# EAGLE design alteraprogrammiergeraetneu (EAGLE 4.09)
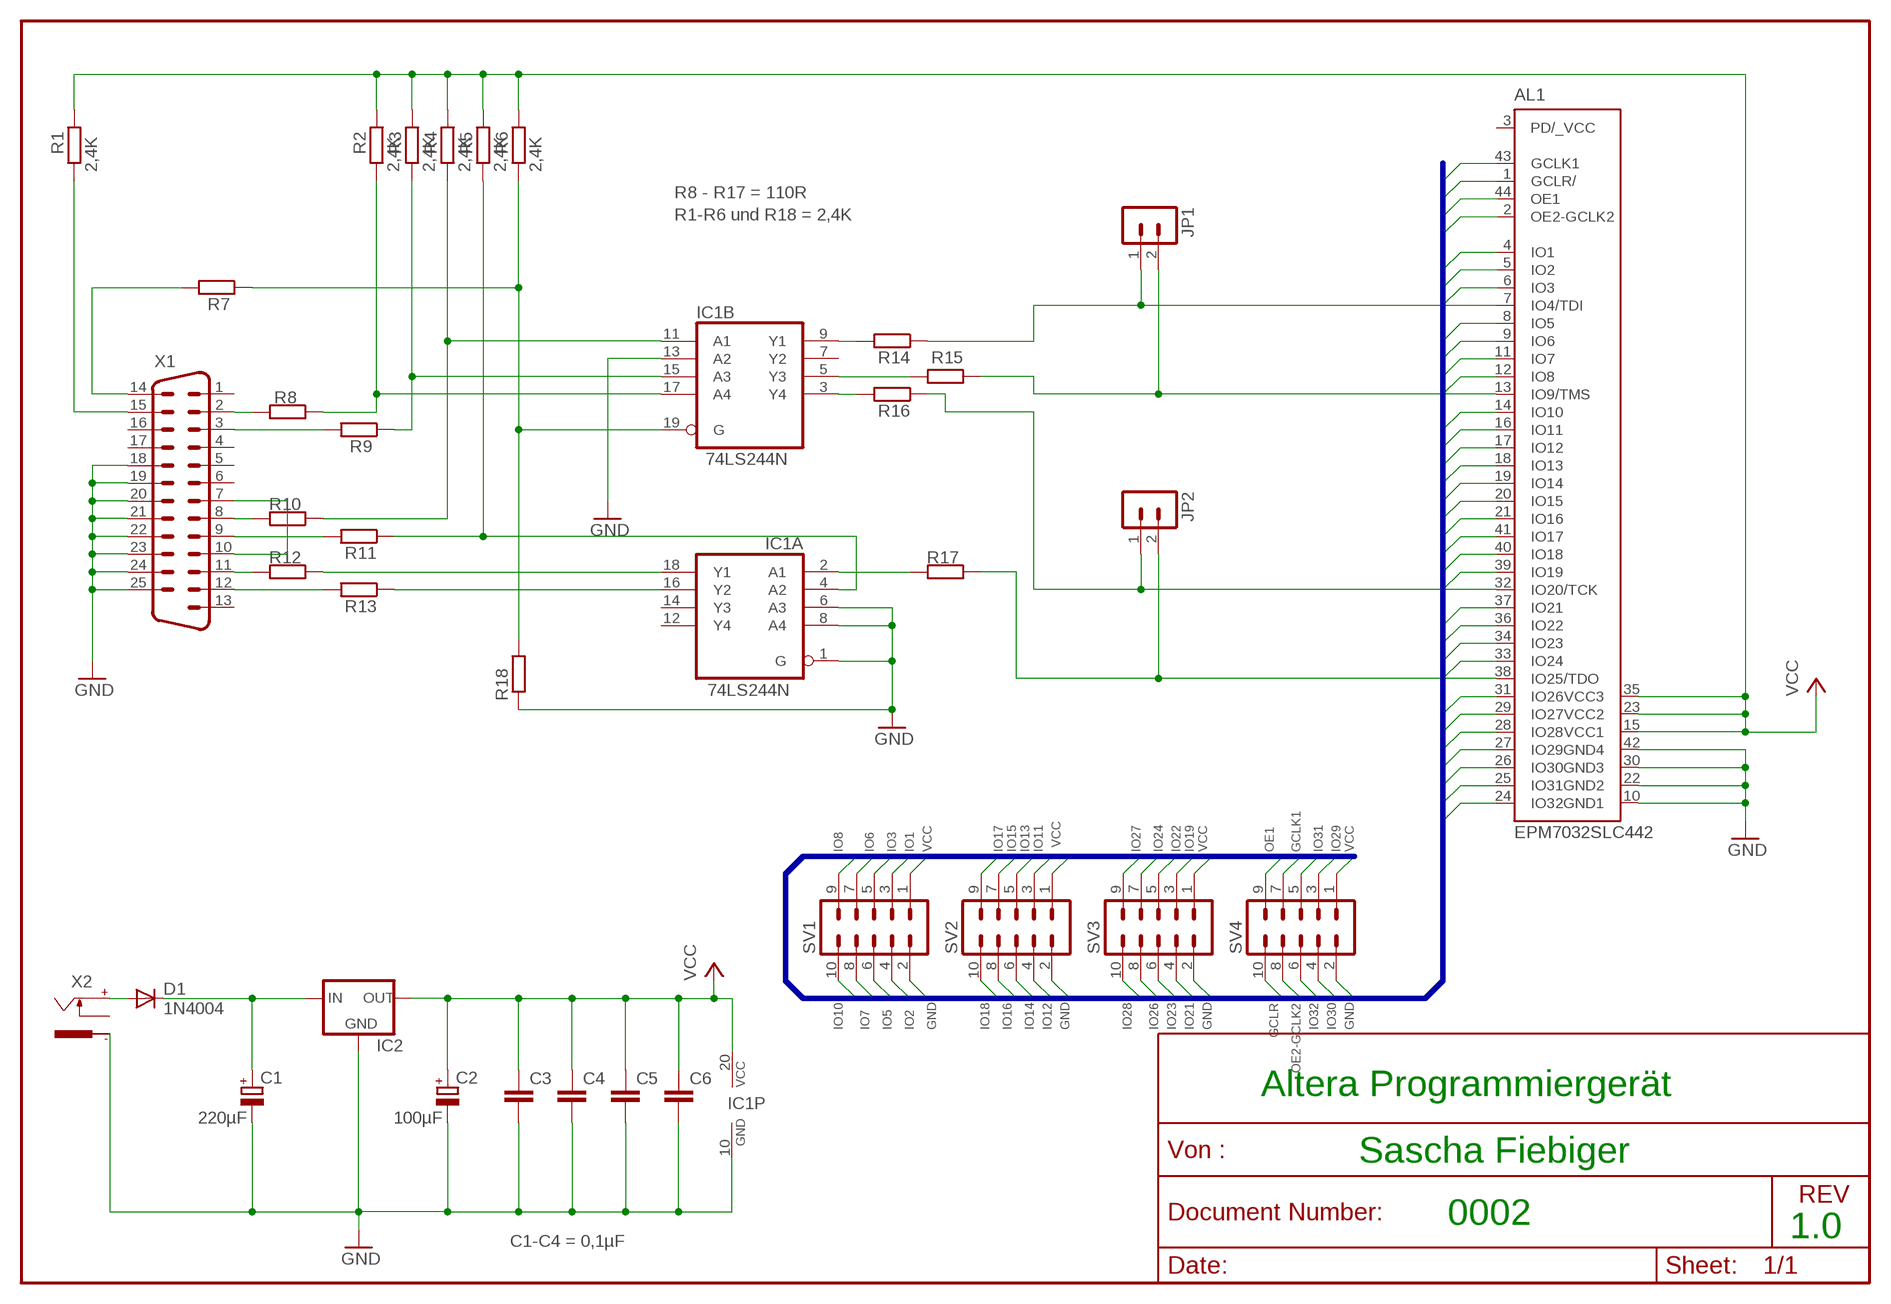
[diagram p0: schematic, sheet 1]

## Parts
AL1  EPM7032SLC442  [PLCC442]
C1  220µF  CPOL-EUE3.5-8  [E3,5-8]
C2  100µF  CPOL-EUE3.5-8  [E3,5-8]
C3  C-EU050-025X075  [C050-025X075]
C4  C-EU050-025X075  [C050-025X075]
C5  C-EU050-025X075  [C050-025X075]
C6  C-EU050-025X075  [C050-025X075]
D1  1N4004  [DO41-10]
IC1  74LS244N  [DIL20]
IC2  78XXS  [78XXS]
JP1  2POL  [2POL]
JP2  2POL  [2POL]
R1  2,4K  R-EU_0207/10  [0207/10]
R2  2,4K  R-EU_0207/10  [0207/10]
R3  2,4K  R-EU_0207/10  [0207/10]
R4  2,4K  R-EU_0207/10  [0207/10]
R5  2,4K  R-EU_0207/10  [0207/10]
R6  2,4K  R-EU_0207/10  [0207/10]
R7  R-EU_0207/10  [0207/10]
R8  R-EU_0207/10  [0207/10]
R9  R-EU_0207/10  [0207/10]
R10  R-EU_0207/10  [0207/10]
R11  R-EU_0207/10  [0207/10]
R12  R-EU_0207/10  [0207/10]
R13  R-EU_0207/10  [0207/10]
R14  R-EU_0207/10  [0207/10]
R15  R-EU_0207/10  [0207/10]
R16  R-EU_0207/10  [0207/10]
R17  R-EU_0207/10  [0207/10]
R18  R-EU_0207/10  [0207/10]
SV1  ML10  [ML10]
SV2  ML10  [ML10]
SV3  ML10  [ML10]
SV4  ML10  [ML10]
X1  M25H  [M25H]
X2  737992-55  [737992-5]

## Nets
GCLK1: AL1.43(GCLK1) SV4.7
GCLR: AL1.1(GCLR/) SV4.10
GND: AL1.10(GND1) AL1.22(GND2) AL1.30(GND3) AL1.42(GND4) C1.- C2.- C3.2 C4.2 C5.2 C6.2 IC1.1(A:G) IC1.6(A:A3) IC1.8(A:A4) IC1.10(P:GND) IC1.13(B:A2) IC2.GND R18.1 SV1.2 SV2.2 SV3.2 SV4.2 X1.18 X1.19 X1.20 X1.21 X1.22 X1.23 X1.24 X1.25 X2.-1
IO1: AL1.4(IO1) SV1.3
IO2: AL1.5(IO2) SV1.4
IO3: AL1.6(IO3) SV1.5
IO5: AL1.8(IO5) SV1.6
IO6: AL1.9(IO6) SV1.7
IO7: AL1.11(IO7) SV1.8
IO8: AL1.12(IO8) SV1.9
IO10: AL1.14(IO10) SV1.10
IO11: AL1.16(IO11) SV2.3
IO12: AL1.17(IO12) SV2.4
IO13: AL1.18(IO13) SV2.5
IO14: AL1.19(IO14) SV2.6
IO15: AL1.20(IO15) SV2.7
IO16: AL1.21(IO16) SV2.8
IO17: AL1.41(IO17) SV2.9
IO18: AL1.40(IO18) SV2.10
IO19: AL1.39(IO19) SV3.3
IO21: AL1.37(IO21) SV3.4
IO22: AL1.36(IO22) SV3.5
IO23: AL1.34(IO23) SV3.6
IO24: AL1.33(IO24) SV3.7
IO26: AL1.31(IO26) SV3.8
IO27: AL1.29(IO27) SV3.9
IO28: AL1.28(IO28) SV3.10
IO29: AL1.27(IO29) SV4.3
IO30: AL1.26(IO30) SV4.4
IO31: AL1.25(IO31) SV4.5
IO32: AL1.24(IO32) SV4.6
N$1: IC1.18(A:Y1) R12.1
N$2: R8.2 X1.2
N$3: R9.2 X1.3
N$4: R10.2 X1.8
N$5: R11.2 X1.9
N$6: R12.2 X1.11
N$7: R13.2 X1.12
N$8: R7.2 X1.14
N$9: R1.1 X1.15
N$10: D1.A X2.+
N$11: IC1.11(B:A1) R4.1 R10.1
N$12: IC1.4(A:A2) R5.1 R11.1
N$13: C1.+ D1.C IC2.IN
N$14: IC1.15(B:A3) R3.1 R9.1
N$15: IC1.17(B:A4) R2.1 R8.1
N$16: IC1.19(B:G) R6.1 R7.1 R18.2
N$17: IC1.16(A:Y2) R13.1
N$22: X1.7 X1.10
N$23: IC1.9(B:Y1) R14.2
N$24: IC1.5(B:Y3) R15.2
N$25: IC1.3(B:Y4) R16.2
N$26: IC1.2(A:A1) R17.2
OE1: AL1.44(OE1) SV4.9
OE2-GCLK2: AL1.2(OE2-GCLK2) SV4.8
TCK: AL1.32(IO20/TCK) JP2.1 R16.1
TDI: AL1.7(IO4/TDI) JP1.1 R14.1
TDO: AL1.38(IO25/TDO) JP2.2 R17.1
TMS: AL1.13(IO9/TMS) JP1.2 R15.1
VCC: AL1.15(VCC1) AL1.23(VCC2) AL1.35(VCC3) C2.+ C3.1 C4.1 C5.1 C6.1 IC1.20(P:VCC) IC2.OUT R1.2 R2.2 R3.2 R4.2 R5.2 R6.2 SV1.1 SV2.1 SV3.1 SV4.1
Unconnected: AL1.3(PD/_VCC) IC1.7(B:Y2) IC1.12(A:Y4) IC1.14(A:Y3) X1.1 X1.4 X1.5 X1.6 X1.13 X1.16 X1.17 X2.-2 X2.K

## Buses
DATEN:IO[1..32],GCLK1,GCLR,OE1,OE2-GCLK2,VCC,GND

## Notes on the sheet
- R8 - R17 = 110R
- R1-R6 und R18 = 2,4K
- Altera Programmiergerät
- Sascha Fiebiger
- 0002
- 1.0
- C1-C4 = 0,1µF

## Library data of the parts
AL1 = ElektroCrew:EPM7032SLC442: Altera EPM7032 Series
C1 C2 = rcl:CPOL-EU: POLARIZED CAPACITOR, European symbol
C3-C6 = rcl:C-EU: CAPACITOR, European symbol
D1 = diode:1N4004: DIODE
IC1 = 74xx-eu:74*244: Octal BUFFER and LINE DRIVER, 3-state
IC2 = v-reg:78XXS: VOLTAGE REGULATOR
JP1 JP2 = ElektroCrew:2POL
R1-R18 = rcl:R-EU_: RESISTOR, European symbol
SV1-SV4 = con-harting-ml:ML10: HARTING
X1 = con-subd:M25: SUB-D
X2 = con-conrad:737992-55: FEMALE PRINT CONNECTOR DIN 45323 (34V/3A), ROKA, distributor Conrad

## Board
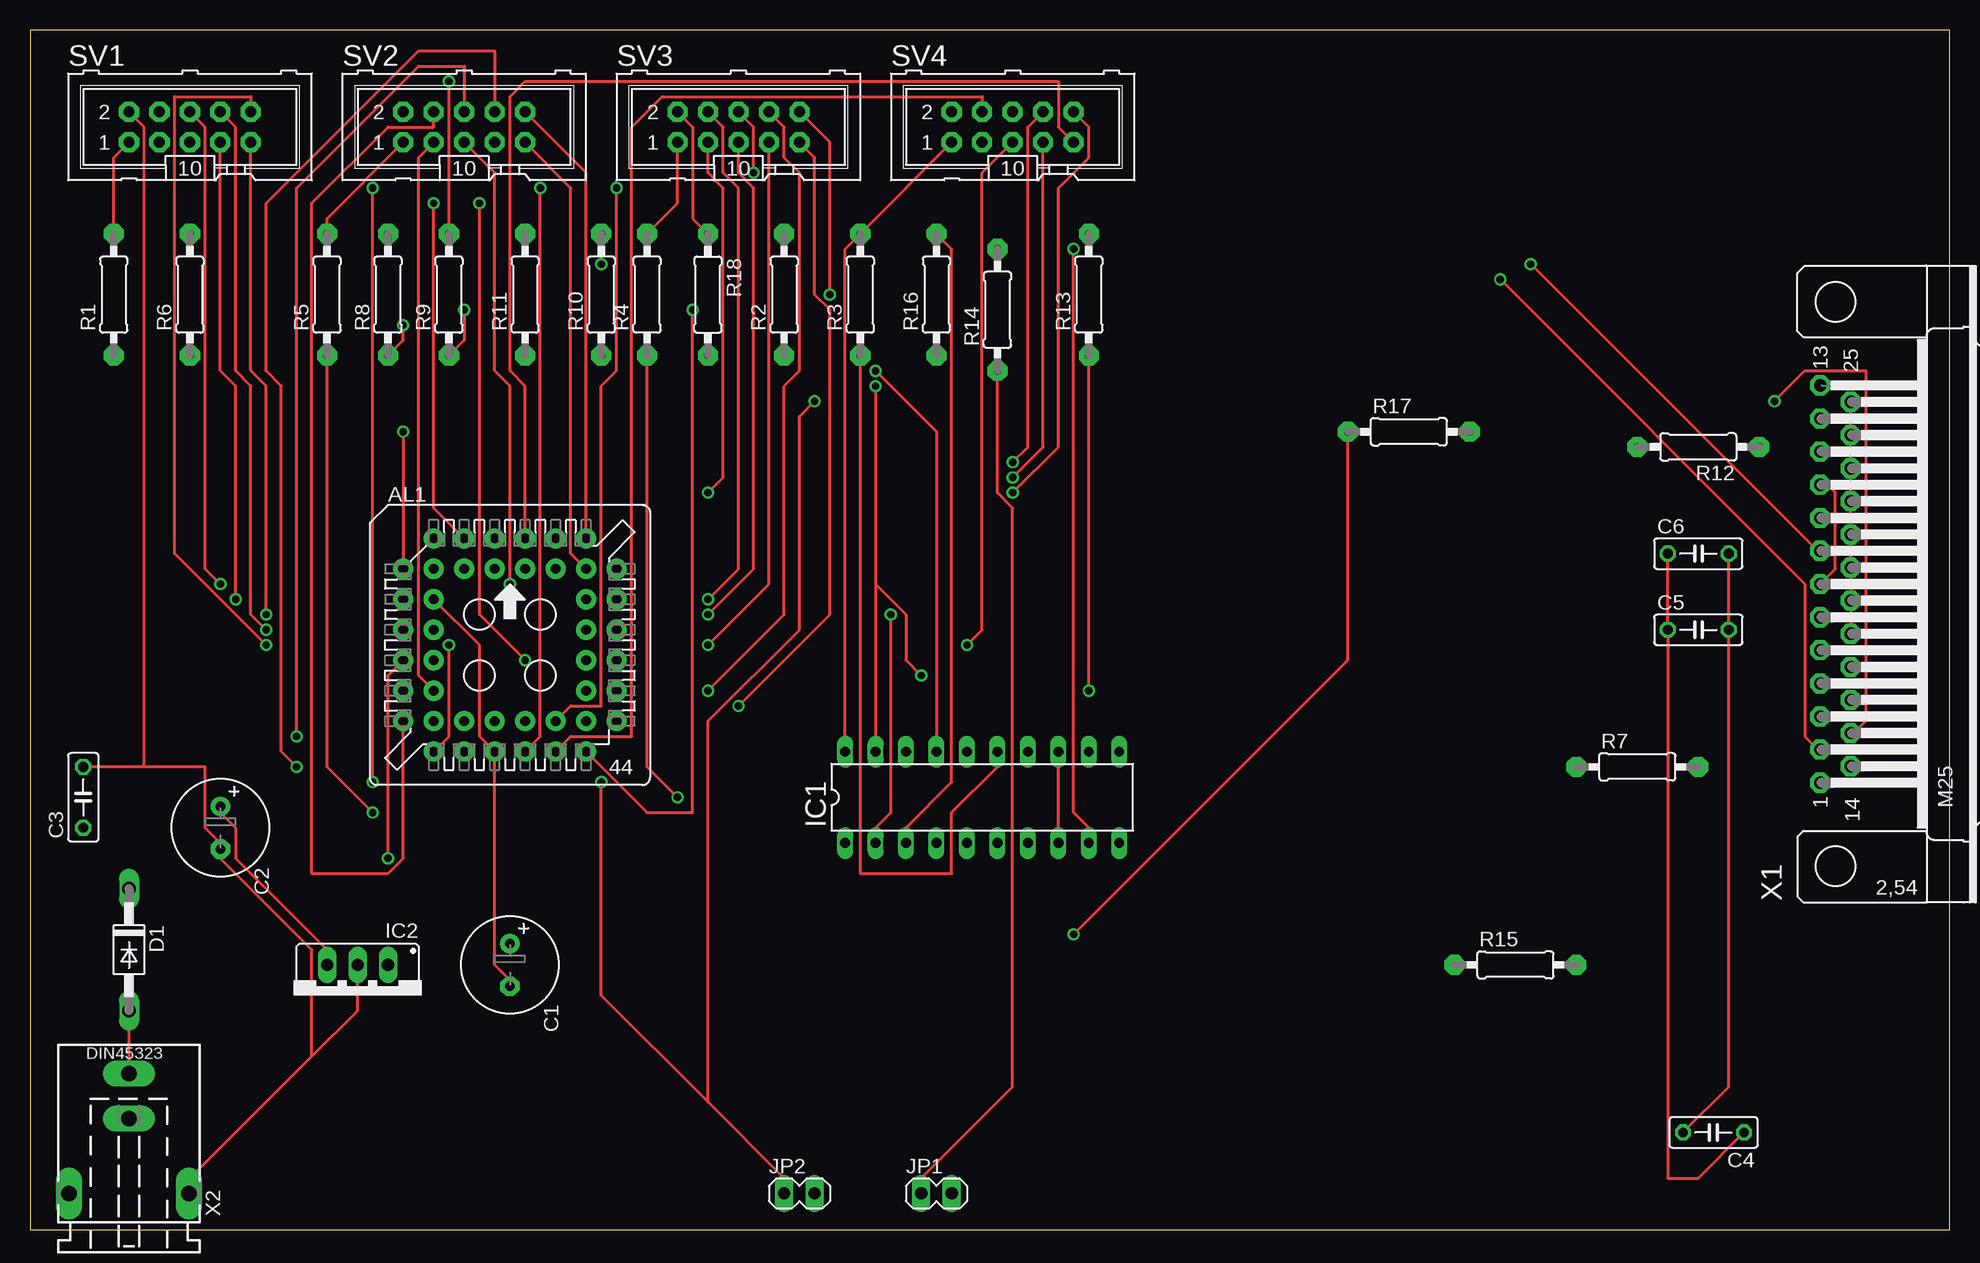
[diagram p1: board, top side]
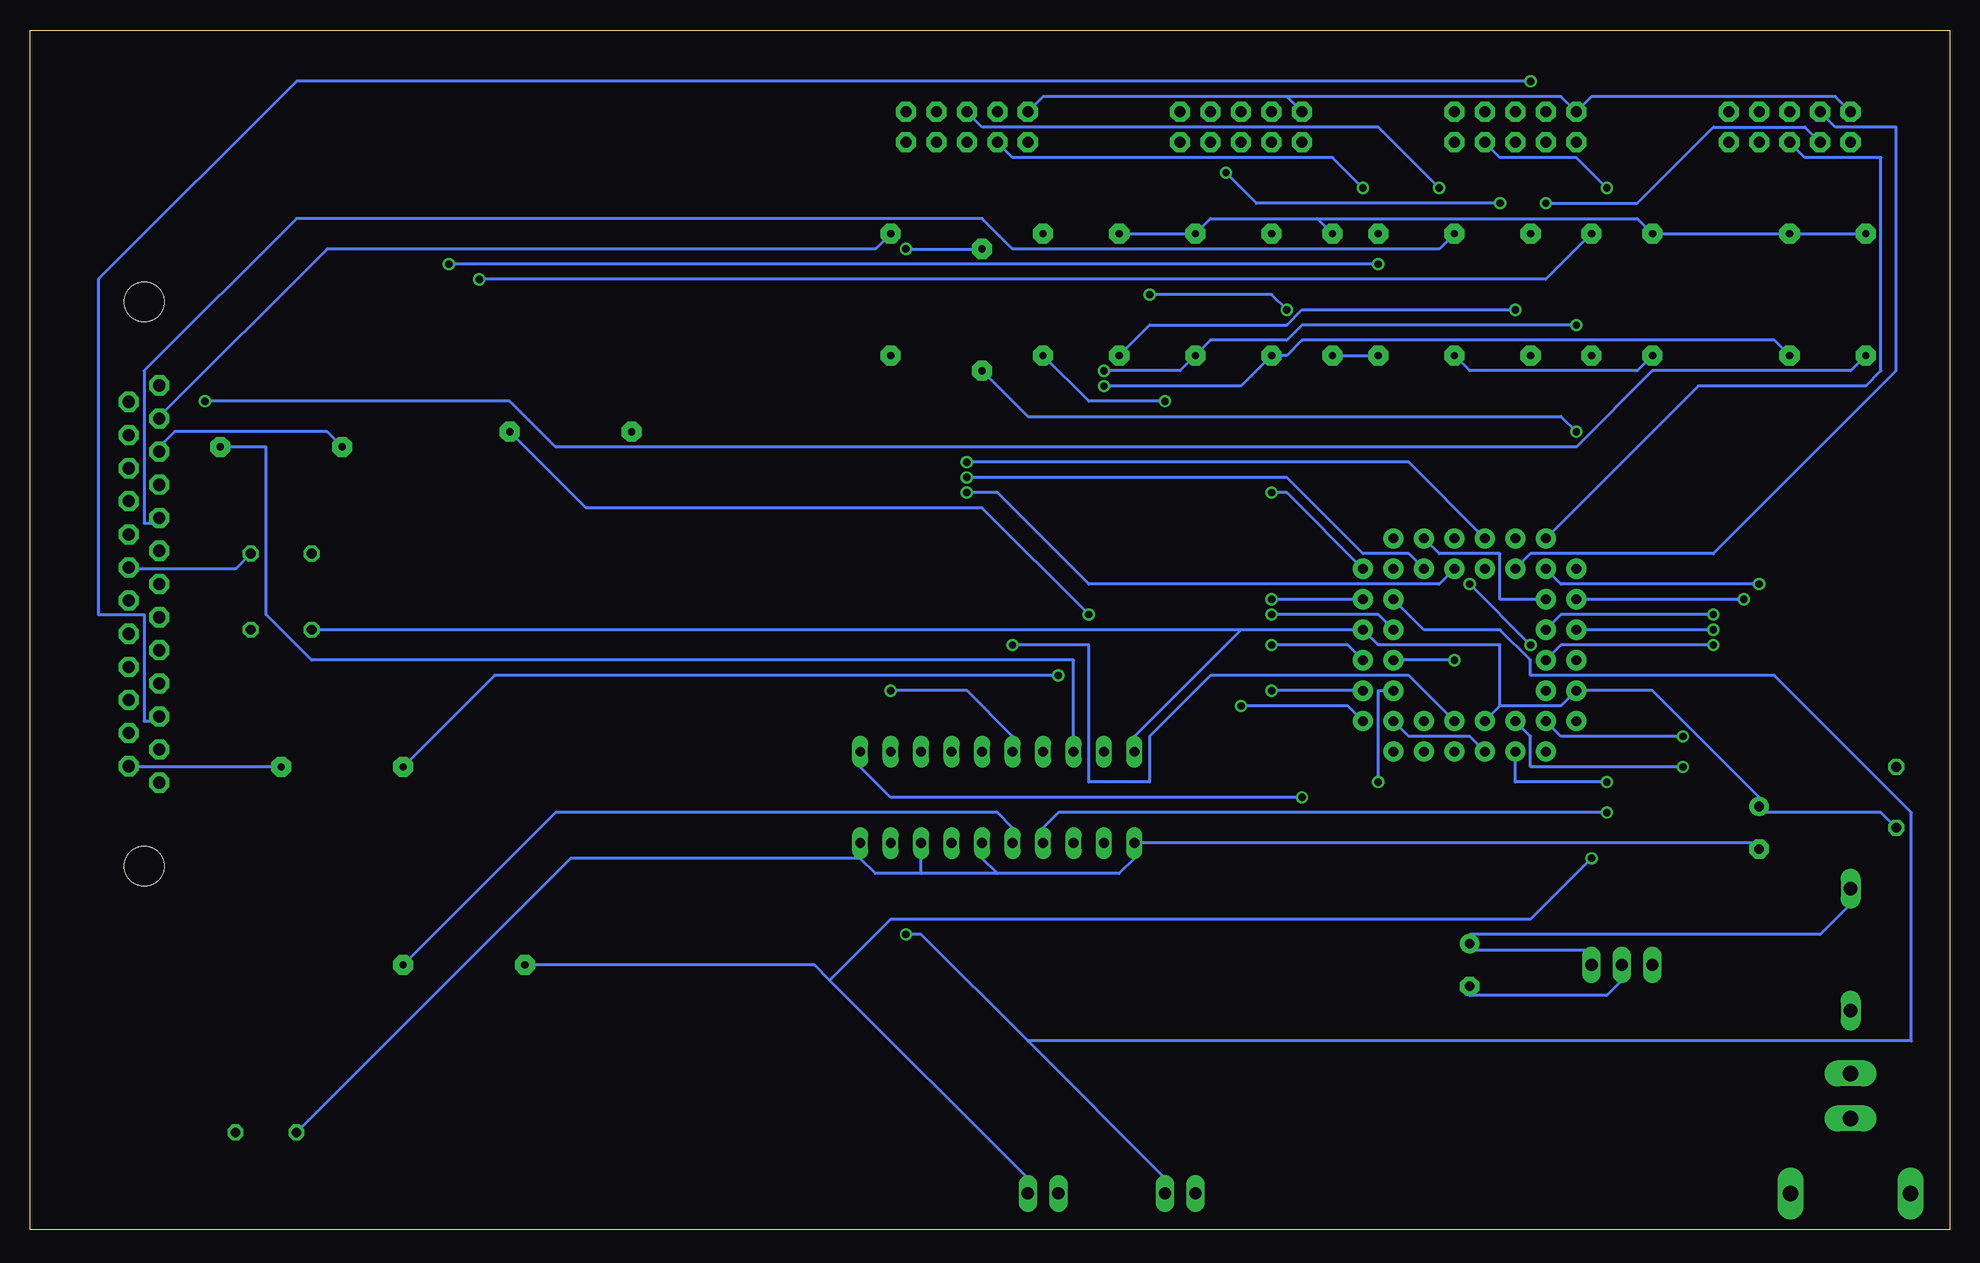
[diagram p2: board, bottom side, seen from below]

Size 160 x 100 mm. Coordinates in mm from the lower left corner, seen from the top.
Outline: 0,0 160,0 160,100 0,100 0,0
Copper layers (1*16): Top 0.035mm / dielectric 1.5mm / Bottom 0.035mm
Design rules "default": minimum track width 10mil, minimum drill 24mil, track to track 8mil, track to pad 8mil, pad to pad 8mil, via to via 8mil, smd to smd 8mil, copper to edge 40mil, drill to drill 8mil, minimum pad ring 10mil, minimum via ring 8mil, stop-mask expansion 4mil, vias tented up to drill 0mil, thermal gap 10mil

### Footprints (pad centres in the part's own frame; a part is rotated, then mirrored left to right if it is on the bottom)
PLCC442 = drill 0.813 pad 1.676 round: 1 1.27,6.35; 2 -1.27,8.89; 3 -1.27,6.35; 4 -3.81,8.89; 5 -3.81,6.35; 6 -6.35,8.89; 7 -8.89,6.35; 8 -6.35,6.35; 9 -8.89,3.81; 10 -6.35,3.81; 11 -8.89,1.27; 12 -6.35,1.27; 13 -8.89,-1.27; 14 -6.35,-1.27; 15 -8.89,-3.81; 16 -6.35,-3.81; 17 -8.89,-6.35; 18 -6.35,-8.89; 19 -6.35,-6.35; 20 -3.81,-8.89; 21 -3.81,-6.35; 22 -1.27,-8.89; 23 -1.27,-6.35; 24 1.27,-8.89; 25 1.27,-6.35; 26 3.81,-8.89; 27 3.81,-6.35; 28 6.35,-8.89; 29 8.89,-6.35; 30 6.35,-6.35; 31 8.89,-3.81; 32 6.35,-3.81; 33 8.89,-1.27; 34 6.35,-1.27; 35 8.89,1.27; 36 6.35,1.27; 37 8.89,3.81; 38 6.35,3.81; 39 8.89,6.35; 40 6.35,8.89; 41 6.35,6.35; 42 3.81,8.89; 43 3.81,6.35; 44 1.27,8.89
E3,5-8 = drill 0.813 pad 1.6 round: + -1.778,0 | drill 0.813 pad 1.6 octagon: - 1.778,0
C050-025X075 = drill 0.813 octagon: 1 -2.54,0; 2 2.54,0
DO41-10 = drill 1.118 long: A 5.08,0; C -5.08,0
DIL20 = drill 0.813 long: 1 -11.43,-3.81; 2 -8.89,-3.81; 3 -6.35,-3.81; 4 -3.81,-3.81; 5 -1.27,-3.81; 6 1.27,-3.81; 7 3.81,-3.81; 8 6.35,-3.81; 9 8.89,-3.81; 10 11.43,-3.81; 11 11.43,3.81; 12 8.89,3.81; 13 6.35,3.81; 14 3.81,3.81; 15 1.27,3.81; 16 -1.27,3.81; 17 -3.81,3.81; 18 -6.35,3.81; 19 -8.89,3.81; 20 -11.43,3.81
78XXS = drill 1.016 long: GND 0,-2.54; IN -2.54,-2.54; OUT 2.54,-2.54
2POL = drill 1.016 long: 1 -1.27,0; 2 1.27,0
0207/10 = drill 0.61 pad 1.676 octagon: 1 -5.08,0; 2 5.08,0
ML10 = drill 0.914 pad 1.676 octagon: 1 -5.08,-1.27; 2 -5.08,1.27; 3 -2.54,-1.27; 4 -2.54,1.27; 5 0,-1.27; 6 0,1.27; 7 2.54,-1.27; 8 2.54,1.27; 9 5.08,-1.27; 10 5.08,1.27
M25H = drill 1.016 pad 1.676 octagon: 1 -16.561,1.27; 2 -13.792,1.27; 3 -11.049,1.27; 4 -8.28,1.27; 5 -5.512,1.27; 6 -2.769,1.27; 7 0,1.27; 8 2.769,1.27; 9 5.512,1.27; 10 8.28,1.27; 11 11.049,1.27; 12 13.792,1.27; 13 16.561,1.27; 14 -15.189,-1.27; 15 -12.421,-1.27; 16 -9.652,-1.27; 17 -6.909,-1.27; 18 -4.14,-1.27; 19 -1.372,-1.27; 20 1.372,-1.27; 21 4.14,-1.27; 22 6.909,-1.27; 23 9.652,-1.27; 24 12.421,-1.27; 25 15.189,-1.27 | hole 3.302: 23.52,0; -23.52,0
737992-5 = drill 1.3 pad 2.184 long: + 0,10; -1 5,0; -2 -5,0; K 0,6.25

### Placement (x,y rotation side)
AL1  40,48.73 0 top
C1  40,22.06 270 top
C2  15.87,33.49 270 top
C3  4.44,36.03 90 top
C4  140.33,8.09 180 top
C5  139.06,50 0 top
C6  139.06,56.35 0 top
D1  8.25,23.33 270 top
IC1  79.37,36.03 0 top
IC2  27.3,19.52 180 top
JP1  75.56,3.01 0 top
JP2  64.13,3.01 0 top
R1  6.98,77.94 90 top
R2  62.86,77.94 90 top
R3  69.21,77.94 90 top
R4  51.43,77.94 90 top
R5  24.76,77.94 90 top
R6  13.33,77.94 90 top
R7  133.98,38.57 0 top
R8  29.84,77.94 90 top
R9  34.92,77.94 90 top
R10  47.62,77.94 90 top
R11  41.27,77.94 90 top
R12  139.06,65.24 180 top
R13  88.26,77.94 90 top
R14  80.64,76.67 90 top
R15  123.82,22.06 0 top
R16  75.56,77.94 90 top
R17  114.93,66.51 0 top
R18  56.51,77.94 270 top
SV1  13.33,91.91 0 top
SV2  36.19,91.91 0 top
SV3  59.05,91.91 0 top
SV4  81.91,91.91 0 top
X1  150.49,53.81 90 top
X2  8.25,3.01 0 top

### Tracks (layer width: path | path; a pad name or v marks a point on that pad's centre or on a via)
GCLK1  (via drill 0.61)
  Top 0.254: v81.91,62.7 84.45,65.24 SV4.7
  Bottom 0.254: AL1.43 45.08,56.35 48.89,56.35 55.24,62.7 v81.91,62.7
GCLR  (via drill 0.61)
  Top 0.254: v81.91,61.43 85.72,65.24 85.72,86.83 88.26,89.37 88.26,91.91 SV4.10
  Bottom 0.254: AL1.1 42.54,53.81 71.75,53.81 79.37,61.43 v81.91,61.43
GND
  Top 0.254: R18.1 55.24,84.29 55.24,91.91 SV3.2 | 151.76,69.05 X1.25 151.76,66.51 X1.24 X1.23 X1.22 X1.21 151.76,57.62 X1.20 151.76,55.08 151.76,52.54 X1.19 X1.18 | C4.2 141.6,11.9 C5.2 C6.2 | AL1.10 37.46,48.73 37.46,41.11 AL1.22 38.73,22.06 40,20.79 C1.- | IC1.8 IC1.13 | 9.52,38.57 14.6,38.57 14.6,33.49 15.87,32.22 C2.- 15.87,30.95 23.49,23.33 23.49,14.44 | 9.52,38.57 C3.2 | 23.49,14.44 27.3,18.25 IC2.GND | 23.49,14.44 13.33,4.28 X2.-1 | SV1.2 9.52,91.91 9.52,38.57
  Bottom 0.254: SV1.2 9.52,94.45 29.84,94.45 SV2.2 32.38,94.45 55.24,94.45 | SV4.2 75.56,94.45 55.24,94.45 | 55.24,94.45 SV3.2 | C6.2 142.87,55.08 151.76,55.08 X1.20 | AL1.22 40,41.11 45.08,41.11 AL1.30 | AL1.42 42.54,56.35 37.46,56.35 37.46,52.54 AL1.10 | 79.37,29.68 69.21,29.68 67.94,30.95 IC1.1 15.87,32.22 C2.- | 79.37,29.68 80.64,30.95 IC1.6 | 90.8,30.95 89.53,29.68 85.72,29.68 | 79.37,29.68 85.72,29.68 | 85.72,29.68 IC1.8 | IC2.GND 27.3,20.79 28.57,19.52 40,19.52 C1.- | C4.2 114.93,30.95 90.8,30.95 | 90.8,30.95 IC1.10
IO1  (via drill 0.61)
  Top 0.254: AL1.4 33.65,60.16 v33.65,85.56
  Bottom 0.254: v33.65,85.56 26.03,85.56 19.68,91.91 12.06,91.91 SV1.3
IO2
  Bottom 0.254: AL1.5 34.92,56.35 19.68,56.35 4.44,71.59 4.44,91.91 9.52,91.91 SV1.4
IO3
  Bottom 0.254: AL1.6 20.95,70.32 6.98,70.32 5.71,71.59 5.71,89.37 12.06,89.37 SV1.5
IO5  (via drill 0.61)
  Top 0.254: v15.87,53.81 14.6,55.08 14.6,91.91 SV1.6
  Bottom 0.254: AL1.8 32.38,53.81 v15.87,53.81
IO6  (via drill 0.61)
  Top 0.254: v17.14,52.54 17.14,70.32 15.87,71.59 SV1.7
  Bottom 0.254: v17.14,52.54 AL1.9
IO7  (via drill 0.61)
  Top 0.254: v19.68,50 18.41,51.27 18.41,70.32 17.14,71.59 17.14,91.91 SV1.8
  Bottom 0.254: v19.68,50 AL1.11
IO8  (via drill 0.61)
  Top 0.254: v19.68,51.27 19.68,70.32 18.41,71.59 SV1.9
  Bottom 0.254: AL1.12 32.38,51.27 v19.68,51.27
IO10  (via drill 0.61)
  Top 0.254: v19.68,48.73 12.06,56.35 12.06,94.45 18.41,94.45 SV1.10
  Bottom 0.254: AL1.14 32.38,48.73 v19.68,48.73
IO11
  Top 0.254: AL1.16 32.38,46.19 32.38,89.37 SV2.3
IO12
  Top 0.254: AL1.17 31.11,30.95 29.84,29.68 23.49,29.68 23.49,85.56 29.84,91.91 33.65,91.91 SV2.4
IO13  (via drill 0.61)
  Top 0.254: AL1.18 34.92,41.11 v34.92,48.73 | v40,53.81 40,70.32 38.73,71.59 38.73,88.1 SV2.5
  Bottom 0.254: v34.92,48.73 v40,53.81
IO14  (via drill 0.61)
  Top 0.254: v22.22,41.11 22.22,86.83 32.38,96.99 36.19,96.99 SV2.6
  Bottom 0.254: AL1.19 32.38,41.11 v22.22,41.11
IO15  (via drill 0.61)
  Top 0.254: v28.57,37.3 v28.57,86.83
  Bottom 0.254: AL1.20 36.19,37.3 v28.57,37.3 | v28.57,86.83 31.11,89.37 37.46,89.37 SV2.7
IO16  (via drill 0.61)
  Top 0.254: v22.22,38.57 20.95,39.84 20.95,70.32 19.68,71.59 19.68,85.56 32.38,98.26 38.73,98.26 SV2.8
  Bottom 0.254: AL1.21 34.92,41.11 34.92,38.57 v22.22,38.57
IO17
  Top 0.254: AL1.41 45.08,56.35 45.08,86.83 SV2.9
IO18
  Top 0.254: AL1.40 46.35,88.1 SV2.10
IO19  (via drill 0.61)
  Top 0.254: v56.51,61.43 57.78,62.7 57.78,86.83 56.51,88.1 SV3.3
  Bottom 0.254: AL1.39 55.24,61.43 v56.51,61.43
IO21  (via drill 0.61)
  Top 0.254: v56.51,52.54 59.05,55.08 59.05,86.83 57.78,88.1 57.78,91.91 SV3.4
  Bottom 0.254: AL1.37 v56.51,52.54
IO22  (via drill 0.61)
  Top 0.254: v56.51,51.27 60.32,55.08 60.32,86.83 59.05,88.1 SV3.5
  Bottom 0.254: AL1.36 47.62,51.27 v56.51,51.27
IO23  (via drill 0.61)
  Top 0.254: v41.27,47.46 37.46,51.27 v37.46,85.56 | v60.32,88.1 60.32,91.91 SV3.6
  Bottom 0.254: v41.27,47.46 AL1.34 | v37.46,85.56 57.78,85.56 v60.32,88.1
IO24  (via drill 0.61)
  Top 0.254: v56.51,48.73 61.59,53.81 SV3.7
  Bottom 0.254: AL1.33 50.16,48.73 v56.51,48.73
IO26  (via drill 0.61)
  Top 0.254: v56.51,44.92 62.86,51.27 62.86,70.32 64.13,71.59 64.13,88.1 62.86,89.37 62.86,91.91 SV3.8
  Bottom 0.254: AL1.31 v56.51,44.92
IO27  (via drill 0.61)
  Top 0.254: v59.05,43.65 66.67,51.27 66.67,76.67 65.4,77.94 65.4,89.37 SV3.9
  Bottom 0.254: AL1.29 50.16,43.65 v59.05,43.65
IO28  (via drill 0.61)
  Top 0.254: AL1.28 51.43,34.76 55.24,34.76 v55.24,76.67 | v66.67,77.94 66.67,90.64 SV3.10
  Bottom 0.254: v55.24,76.67 56.51,77.94 v66.67,77.94
IO29  (via drill 0.61)
  Top 0.254: AL1.27 45.08,43.65 47.62,43.65 47.62,70.32 48.89,71.59 v48.89,86.83
  Bottom 0.254: v48.89,86.83 51.43,89.37 78.1,89.37 SV4.3
IO30
  Top 0.254: AL1.26 45.08,41.11 50.16,41.11 50.16,91.91 52.7,94.45 79.37,94.45 SV4.4
IO31  (via drill 0.61)
  Top 0.254: v78.1,48.73 79.37,50 79.37,88.1 SV4.5
  Bottom 0.254: AL1.25 45.08,46.19 61.59,46.19 66.67,41.11 66.67,37.3 71.75,37.3 71.75,48.73 v78.1,48.73
IO32  (via drill 0.61)
  Top 0.254: AL1.24 42.54,41.11 v42.54,86.83
  Bottom 0.254: v42.54,86.83 47.62,91.91 80.64,91.91 SV4.6
N$1
  Bottom 0.254: R12.1 140.33,65.24 140.33,51.27 136.52,47.46 73.02,47.46 IC1.18
N$2  (via drill 0.61)
  Top 0.254: v122.55,79.21 147.95,53.81 147.95,41.11 149.22,39.84 X1.2
  Bottom 0.254: R8.2 33.65,79.21 v122.55,79.21
N$3  (via drill 0.61)
  Top 0.254: R9.2 v34.92,95.72
  Bottom 0.254: v34.92,95.72 137.79,95.72 154.3,79.21 154.3,51.27 150.49,51.27 150.49,42.38 149.22,42.38 X1.3
N$4  (via drill 0.61)
  Top 0.254: v47.62,80.48 R10.2 | v125.09,80.48 149.22,56.35 X1.8
  Bottom 0.254: v47.62,80.48 v125.09,80.48
N$5
  Bottom 0.254: R11.2 42.54,81.75 78.1,81.75 80.64,84.29 137.79,84.29 150.49,71.59 150.49,58.89 149.22,58.89 X1.9
N$6
  Bottom 0.254: R12.2 135.25,66.51 147.95,66.51 149.22,65.24 X1.11
N$7
  Bottom 0.254: R13.2 89.53,81.75 135.25,81.75 149.22,67.78 X1.12
N$8
  Bottom 0.254: R7.2 151.76,38.57 X1.14
N$9  (via drill 0.61)
  Top 0.254: v145.41,69.05 147.95,71.59 153.03,71.59 153.03,42.38 151.76,41.11 X1.15
  Bottom 0.254: R1.1 8.25,71.59 24.76,71.59 31.11,65.24 116.2,65.24 120.01,69.05 v145.41,69.05
N$10
  Top 0.254: X2.+ D1.A
N$11  (via drill 0.61)
  Top 0.254: v53.97,36.03 51.43,38.57 R4.1
  Bottom 0.254: v53.97,36.03 88.26,36.03 90.8,38.57 IC1.11 | R4.1 R10.1
N$12  (via drill 0.61)
  Top 0.254: v28.57,34.76 24.76,38.57 R5.1
  Bottom 0.254: v28.57,34.76 74.29,34.76 75.56,33.49 IC1.4 | R11.1 40,71.59 26.03,71.59 R5.1
N$13
  Bottom 0.254: IC2.IN 29.84,23.33 40,23.33 C1.+ 40,24.6 10.79,24.6 8.25,27.14 D1.C
N$14  (via drill 0.61)
  Top 0.254: R3.1 69.21,29.68 76.83,29.68 76.83,34.76 80.64,38.57 IC1.15 | R9.1 36.19,74.13 v36.19,76.67
  Bottom 0.254: v36.19,76.67 53.97,76.67 55.24,75.4 66.67,75.4 R3.1
N$15  (via drill 0.61)
  Top 0.254: v70.48,71.59 75.56,66.51 IC1.17 | R8.1 31.11,74.13 v31.11,75.4
  Bottom 0.254: v70.48,71.59 64.13,71.59 R2.1 61.59,74.13 55.24,74.13 53.97,75.4 v31.11,75.4
N$16  (via drill 0.61)
  Top 0.254: v70.48,70.32 70.48,53.81 | 70.48,53.81 IC1.19 | v74.29,46.19 73.02,47.46 73.02,51.27 70.48,53.81
  Bottom 0.254: v70.48,70.32 59.05,70.32 R18.2 55.24,72.86 53.97,74.13 14.6,74.13 R6.1 | R7.1 121.28,46.19 v74.29,46.19
N$17  (via drill 0.61)
  Top 0.254: v88.26,44.92 R13.1
  Bottom 0.254: v88.26,44.92 81.91,44.92 78.1,41.11 IC1.16
N$22
  Top 0.254: X1.7 150.49,55.08 150.49,61.43 149.22,62.7 X1.10
N$23  (via drill 0.61)
  Top 0.254: v86.99,81.75 86.99,34.76 88.26,33.49 IC1.9
  Bottom 0.254: v86.99,81.75 R14.2
N$24
  Bottom 0.254: R15.2 116.2,34.76 79.37,34.76 78.1,33.49 IC1.5
N$25
  Top 0.254: R16.2 76.83,81.75 76.83,37.3 73.02,33.49 IC1.3
N$26  (via drill 0.61)
  Top 0.254: v71.75,51.27 71.75,34.76 70.48,33.49 IC1.2
  Bottom 0.254: v71.75,51.27 80.64,60.16 113.66,60.16 R17.2
OE1
  Top 0.254: AL1.44 41.27,70.32 40,71.59 40,94.45 41.27,95.72 85.72,95.72 85.72,91.91 SV4.9
OE2-GCLK2  (via drill 0.61)
  Top 0.254: v81.91,63.97 83.18,65.24 83.18,91.91 SV4.8
  Bottom 0.254: AL1.2 45.08,63.97 v81.91,63.97
TCK  (via drill 0.61)
  Top 0.254: 56.51,10.63 47.62,19.52 v47.62,37.3 | 56.51,10.63 62.86,4.28 JP2.1 | v65.4,69.05 64.13,67.78 64.13,50 56.51,42.38 56.51,10.63
  Bottom 0.254: v47.62,37.3 47.62,44.92 AL1.32 | R16.1 71.75,69.05 v65.4,69.05
TDI  (via drill 0.61)
  Top 0.254: R14.1 80.64,61.43 81.91,60.16 81.91,11.9 74.29,4.28 JP1.1 | v31.11,66.51 AL1.7
  Bottom 0.254: v31.11,66.51 32.38,67.78 76.83,67.78 R14.1
TDO  (via drill 0.61)
  Top 0.254: v86.99,24.6 109.85,47.46 R17.1
  Bottom 0.254: 76.83,15.71 85.72,24.6 v86.99,24.6 | 76.83,15.71 65.4,4.28 JP2.2 | AL1.38 43.81,50 37.46,50 34.92,47.46 34.92,46.19 14.6,46.19 3.17,34.76 3.17,15.71 76.83,15.71
TMS  (via drill 0.61)
  Top 0.254: AL1.13 29.84,46.19 v29.84,30.95
  Bottom 0.254: 93.34,20.79 94.61,22.06 R15.1 | 93.34,20.79 76.83,4.28 JP1.2 | v29.84,30.95 34.92,25.87 88.26,25.87 93.34,20.79
VCC
  Top 0.254: SV1.1 6.98,89.37 R1.2 | SV2.1 24.76,84.29 R5.2 | R4.2 53.97,85.56 SV3.1 | SV4.1 R3.2 67.94,81.75 IC1.20 | C6.1 C5.1 136.52,4.28 139.06,4.28 C4.1 | IC2.OUT 24.76,23.33 17.14,30.95 17.14,33.49 15.87,34.76 C2.+
  Bottom 0.254: R1.2 R6.2 R5.2 26.03,84.29 52.7,84.29 | R3.2 R2.2 61.59,84.29 52.7,84.29 | 52.7,84.29 R4.2 | C3.1 5.71,34.76 15.87,34.76 C2.+ 15.87,36.03 24.76,44.92 AL1.15 32.38,43.65 37.46,43.65 | 37.46,43.65 AL1.23 | 59.05,50 67.94,41.11 IC1.20 | 59.05,50 AL1.35 47.62,48.73 37.46,48.73 37.46,43.65 | 59.05,50 C5.1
